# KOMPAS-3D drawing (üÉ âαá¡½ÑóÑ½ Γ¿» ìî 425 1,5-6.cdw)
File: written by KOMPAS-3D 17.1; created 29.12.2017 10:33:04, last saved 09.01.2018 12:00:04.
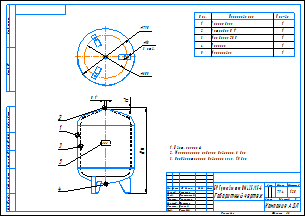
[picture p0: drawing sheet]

Sheet 1: A3, landscape, title-block layout from C:\Лощинин\GRAPHIC.LYT style 1

Title block, sheet 1: name: БР Гранлевел тип НМ 425/1,5-6 / Габаритный чертеж; mass: 79,4; sheets: 1; sheet format: A3; stored path: \\Fsk1\files\АП\20_PKO\02_Насосное направление\Разработка\04_Проекты разные\Баки\КД действующая\Баки Flexcon R\Компас\Чертежи\БР Гранлевел тип НМ 425 1,5-6.cdw; drawn by: Лощинин; checked by: Хантимеров

Views: Проекционный вид 2
Referenced files in \\Fsk1\files\АП\20_PKO\02_Насосное направление\Разработка\04_Проекты разные\Баки\КД действующая\Баки Flexcon R\Компас\: 425 литров.a3d, 16422_Flexcon_425_1-6.m3d
Referenced files in C:\Лощинин\: GRAPHIC.LYT
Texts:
  IvAn
  ADL
  Поз.
  Кол-во
  Корпус бака
  Мембрана SBR
  Патрубок G 1"
  Ниппель
  Маркировка
  АДЛ
  Цвет: красный
  Максимальное рабочее давление: 6 бар
  Предварительное давление газа: 1,5 бар
  ACAD_ISO03W100_RGB_223_127_255_SC_0.063_THICK_0.05
  ACAD_ISO03W100_RGB_223_127_255_SC_1_THICK_0.05
  Лит-Масса-Масштаб
  Материал-Предприятие
  Масштаб
  Изм.
  Лист
  № докум.
  Подп.
  Дата
  Лит.
  Разраб.
  Пров.
  Т.контр.
  Курлыкина
  Листов
  Нач.отд.
  Щетинин
  Н.контр.
  Долгов
  Утв.
  Рашидов
  Компания АДЛ
  Изменение
  Номер документа
  Подпись
  Обозначение документа
  Наименование изделия
  Масса изделия по ГОСТ 2.109-73
  Порядковый номер листа
  Общее количество листов в документе
  Характер работы, выполненной лицом, подписавшим документ
  Наименование или индекс предприятия, выпускающего документ
  Инв. № подл.
  Подп. и дата
  Взам. инв. №
  Инв. № дубл.
  Инвентарный номер подлинника по ГОСТ 2.501-68
  Подпись принявшего подлинник в отдел технической документации
  Инвентарный номер подлинника, взамен которого выпущен данный подлинник
  Инвентарный номер дубликата по ГОСТ 2.502-68
  Подпись принявшего дубликат в отдел технической документации
  Справ. №
  Перв. примен.
  Обозначение документа, взамен или на основании которого выпущен данный документ
  Обозначение документа, в котором впервые записан данный документ
  Подпись лица, копировавшего чертеж
  Обозначение формата листа
Dimensions and other numbers on the sheet: 1; 3; 2; 4; 5; 21; 1:20; 79,4; 16422_Flexcon_425_1-6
